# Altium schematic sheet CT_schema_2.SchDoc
size 321 x 189 mm
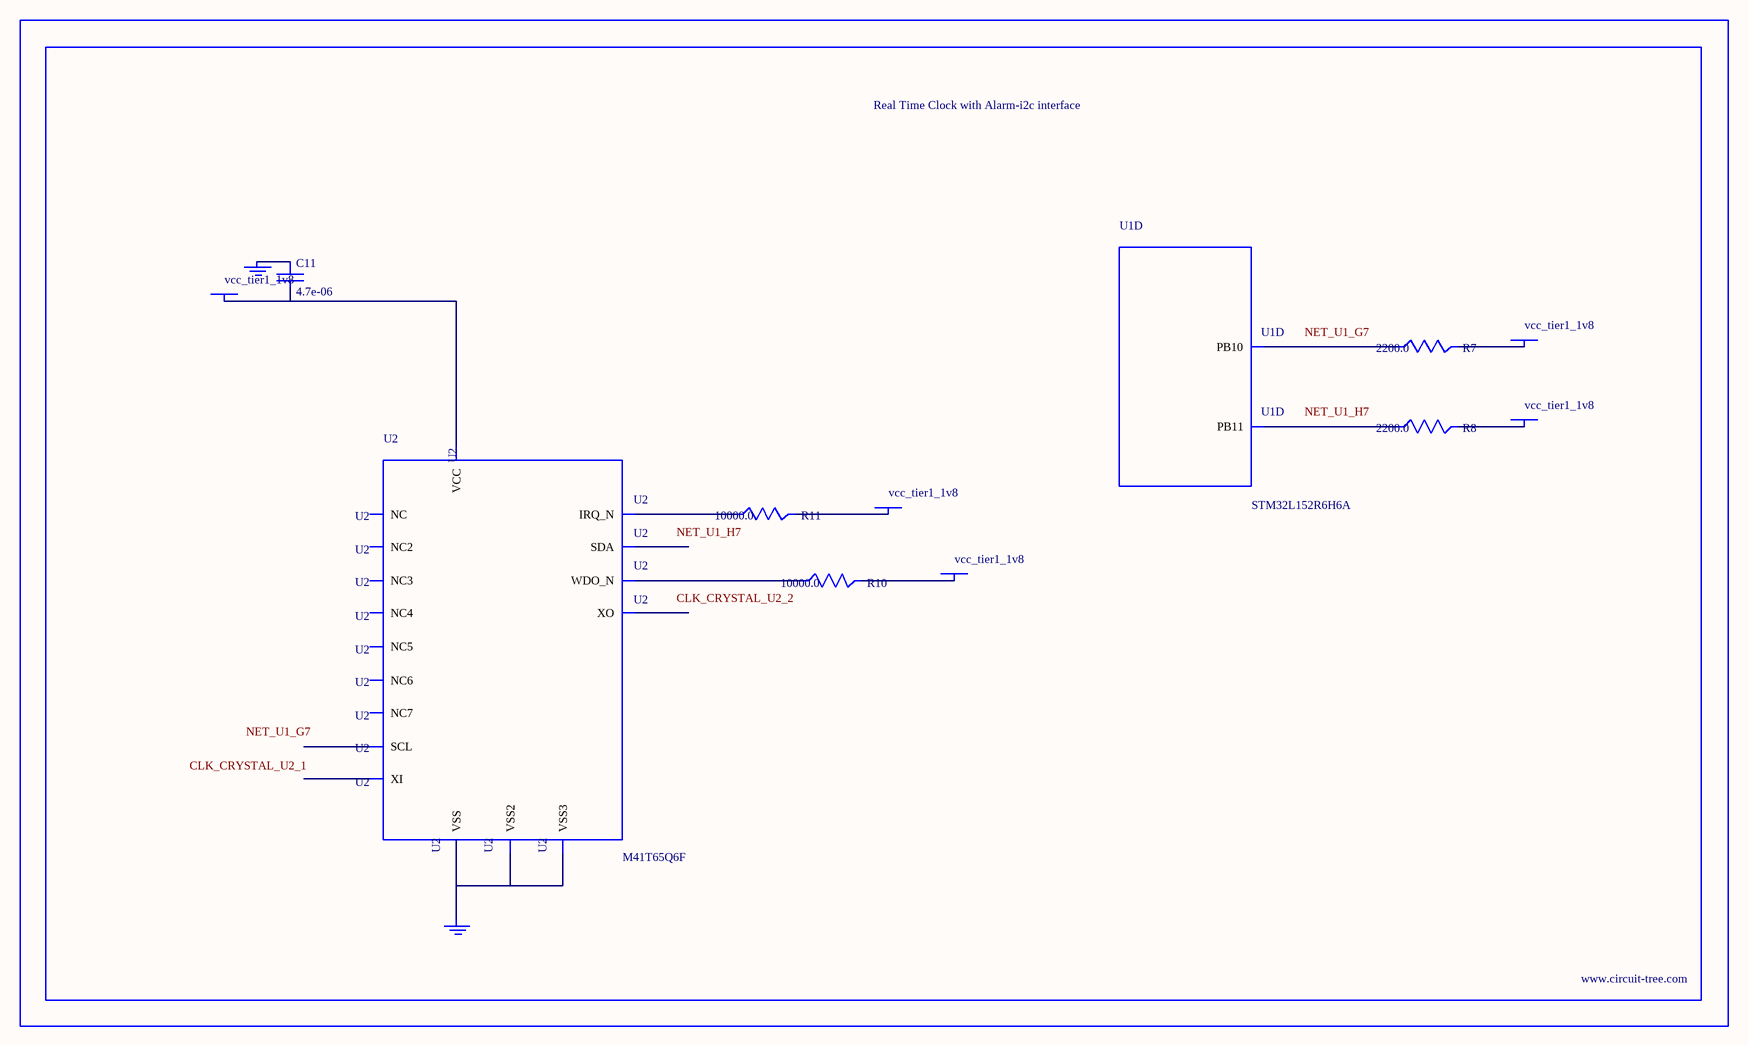
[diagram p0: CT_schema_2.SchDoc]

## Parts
BORDER1  (no value)
C11  4.7e-06  [C0805]
GND_INSTANCE_1_0  (no value)
GND_INSTANCE_1_1  (no value)
POWER_INSTANCE_1_0  vcc_tier1_1v8
POWER_INSTANCE_1_1  vcc_tier1_1v8
POWER_INSTANCE_1_2  vcc_tier1_1v8
POWER_INSTANCE_1_3  vcc_tier1_1v8
POWER_INSTANCE_1_4  vcc_tier1_1v8
R7  2200.0  [R0603]
R8  2200.0  [R0603]
R10  10000.0  [R0603]
R11  10000.0  [R0603]
U1  STM32L152R6H6A  [TFBGA64]  (part D of 7)
U2  M41T65Q6F  [M41T65_QFN-16]

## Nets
NetC11_1: C11.1 GND_INSTANCE_1_0.0(GND)
NetC11_2: C11.2 POWER_INSTANCE_1_2.0(PWR) U2.14(VCC)
NetGND_INSTANCE_1_1_0: GND_INSTANCE_1_1.0(GND) U2.3(VSS) U2.5(VSS2) U2.17(VSS3)
NetPOWER_INSTANCE_1_0_0: POWER_INSTANCE_1_0.0(PWR) R10.2
NetPOWER_INSTANCE_1_1_0: POWER_INSTANCE_1_1.0(PWR) R11.2
NetPOWER_INSTANCE_1_3_0: POWER_INSTANCE_1_3.0(PWR) R7.2
NetPOWER_INSTANCE_1_4_0: POWER_INSTANCE_1_4.0(PWR) R8.2
NetR7_1: R7.1 U1.G7(PB10)
NetR8_1: R8.1 U1.H7(PB11)
NetR10_1: R10.1 U2.4(WDO_N)
NetR11_1: R11.1 U2.11(IRQ_N)

Not connected (* = marked no-connect by the designer): U2 1(XI) 2(XO) 6(NC) 7(NC2) 8(NC3) 9(SDA) 10(SCL) 12(NC4) 13(NC5) 15(NC6) 16(NC7)

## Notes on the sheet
- Labels drawn without touching a wire or pin: CLK_CRYSTAL_U2_1, CLK_CRYSTAL_U2_2, NET_U1_G7, NET_U1_H7

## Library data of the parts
BORDER1 = BORDER_PAGE1
C11 = C0805C475K4RACTU
GND_INSTANCE_1_0 GND_INSTANCE_1_1 = GND
POWER_INSTANCE_1_0-POWER_INSTANCE_1_4 = PWR
R7 R8 = RC0603JR-072K2L
R10 R11 = RC0603JR-0710KL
